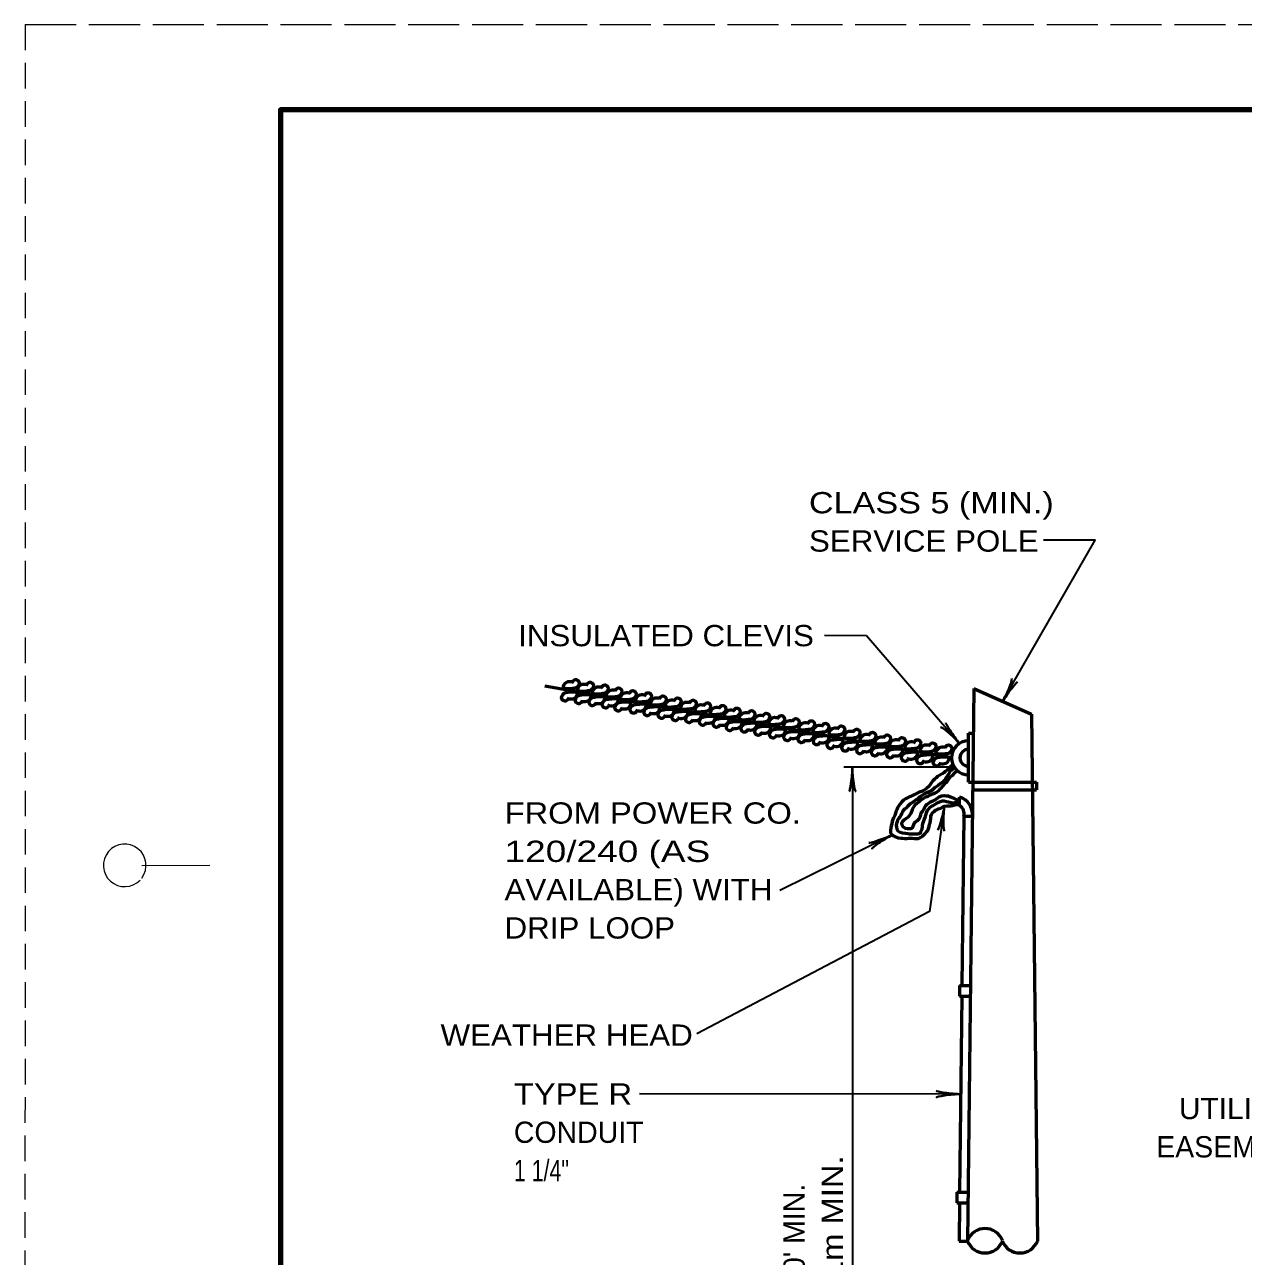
# Model space of a CAD drawing. Extents: x -68 to 612, y -58 to 382.
# Drawn here: x -67.7 to 75.5, y 237.5 to 382.2 of the extents above; entities that cross this region are included whole.
import ezdxf
from ezdxf.enums import TextEntityAlignment as Align

# ---------------------------------------------------------------- set-up
doc = ezdxf.new("R2010")
doc.units = 0
doc.linetypes.add('LONG_DASHED', pattern=[7.5, 6, -1.5])
doc.linetypes.add('MEDIUM_DASHED', pattern=[4.5, 3, -1.5])
doc.layers.add('1', color=7, linetype='Continuous', lineweight=53)
doc.layers.add('61', color=7, linetype='Continuous', lineweight=35)

msp = doc.modelspace()

# ---------------------------------------------------------------- linework, layer by layer
at = {"layer": '1', "linetype": 'MEDIUM_DASHED', "lineweight": 13}
msp.add_line((-67.611, 382.166), (-67.671, -57.874), dxfattribs=at)
at = {"layer": '1', "lineweight": 35}
for p, q in [((31.222, 310.386), (26.284, 310.397)), ((42.124, 297.726), (31.222, 310.386)), ((41.57, 294.939), (28.57, 294.939)), ((34.265, 286.976), (21.04, 280.461)), ((42.283, 256.525), (4.547, 256.554))]:
    msp.add_line(p, q, dxfattribs=at)
at = {"layer": '1'}
for p, q in [((41.199, 296.039), (-6.564, 304.461)), ((43.824, 304.163), (43.087, 239.264)), ((43.824, 304.163), (50.588, 301.163)), ((50.588, 301.163), (51.291, 239.264)), ((43.199, 298.914), (43.764, 298.914)), ((43.199, 293.164), (43.199, 298.914)), ((43.199, 293.164), (51.189, 293.164)), ((51.189, 293.164), (51.189, 292.264)), ((42.154, 290.426), (42.154, 291.426)), ((43.689, 292.264), (51.189, 292.264)), ((42.654, 289.176), (42.428, 269.275)), ((42.654, 289.176), (43.654, 289.176)), ((42.163, 269.275), (43.413, 269.275)), ((42.163, 269.275), (42.163, 268.025)), ((42.413, 268.025), (42.152, 245.025)), ((42.163, 268.025), (43.413, 268.025)), ((41.837, 245.025), (43.087, 245.025)), ((41.837, 245.025), (41.837, 243.775)), ((41.837, 243.775), (43.087, 243.775)), ((42.138, 243.775), (42.087, 239.275)), ((42.087, 239.275), (43.087, 239.275))]:
    msp.add_line(p, q, dxfattribs=at)
at = {"layer": '1', "lineweight": 35}
for points in [[(47.206, 302.663), (58.076, 321.589), (52.012, 321.589)], [(29.57, 294.939), (29.57, 176.275), (29.57, 116.264)], [(40.381, 290.343), (38.621, 277.993), (11.274, 263.595)]]:
    msp.add_lwpolyline(points, dxfattribs=at)
at = {"layer": '1'}
for points in [[(41.388, 295.302), (41.227, 295.14), (41.106, 295.02), (40.965, 294.858), (40.804, 294.697), (40.683, 294.576), (40.481, 294.435), (40.32, 294.274), (40.099, 294.173), (39.837, 293.991), (39.554, 293.83), (39.393, 293.669), (39.212, 293.528), (39.01, 293.326), (38.91, 293.185), (38.728, 292.943), (38.527, 292.681), (38.305, 292.48), (38.103, 292.318), (37.862, 292.177), (37.7, 292.097), (37.519, 292.036), (37.338, 291.955), (37.176, 291.875), (36.995, 291.774), (36.814, 291.693), (36.612, 291.593), (36.391, 291.512), (36.189, 291.411), (35.988, 291.31), (35.806, 291.21), (35.564, 291.048), (35.363, 290.847), (35.161, 290.625), (35.02, 290.403), (34.879, 290.161), (34.779, 289.92), (34.678, 289.698), (34.617, 289.496), (34.537, 289.254), (34.396, 288.992), (34.315, 288.791), (34.255, 288.549), (34.194, 288.287), (34.134, 288.045), (34.073, 287.783), (34.033, 287.541), (34.053, 287.218), (34.154, 287.077), (34.376, 286.876), (34.537, 286.775), (34.758, 286.714), (34.96, 286.654), (35.262, 286.614), (35.464, 286.594), (35.726, 286.573), (35.947, 286.573), (36.169, 286.594), (36.37, 286.594), (36.592, 286.614), (36.854, 286.573), (37.156, 286.553), (37.338, 286.573), (37.559, 286.674), (37.781, 286.835), (37.962, 286.976), (38.103, 287.158), (38.285, 287.339), (38.426, 287.501), (38.506, 287.743), (38.567, 287.984), (38.627, 288.226), (38.708, 288.408), (38.748, 288.67), (38.768, 288.932), (38.789, 289.194), (38.869, 289.395), (38.99, 289.577), (39.172, 289.738), (39.333, 289.899), (39.514, 289.98), (39.695, 290.061), (39.937, 290.141), (40.179, 290.262), (40.381, 290.343), (40.703, 290.403), (40.905, 290.383), (41.126, 290.403), (41.368, 290.444), (41.61, 290.504), (41.811, 290.544), (42.033, 290.565), (42.114, 290.585)], [(41.57, 294.939), (41.207, 294.596), (41.066, 294.455), (40.844, 294.133), (40.683, 293.891), (40.562, 293.729), (40.441, 293.427), (40.26, 293.266), (40.058, 293.125), (39.857, 292.963), (39.635, 292.782), (39.413, 292.641), (39.192, 292.52), (39.01, 292.298), (38.849, 292.177), (38.506, 291.996), (38.224, 291.895), (38.023, 291.794), (37.862, 291.673), (37.68, 291.572), (37.499, 291.452), (37.297, 291.27), (37.156, 291.169), (36.975, 291.048), (36.794, 290.907), (36.491, 290.726), (36.35, 290.625), (36.229, 290.504), (36.048, 290.303), (35.867, 290.121), (35.685, 290), (35.544, 289.839), (35.444, 289.657), (35.343, 289.456), (35.262, 289.274), (35.141, 289.073), (35, 288.932), (34.879, 288.73), (34.819, 288.529), (34.758, 288.327), (34.718, 288.105), (34.738, 287.884), (34.799, 287.642), (34.899, 287.44), (35.161, 287.299), (35.444, 287.238), (35.806, 287.178), (36.068, 287.138), (36.27, 287.118), (36.572, 287.097), (36.773, 287.097), (37.015, 287.097), (37.257, 287.118), (37.459, 287.158), (37.6, 287.299), (37.66, 287.46), (37.761, 287.682), (37.781, 287.924), (37.801, 288.105), (37.841, 288.307), (37.902, 288.529), (38.003, 288.77), (38.124, 289.033), (38.204, 289.315), (38.285, 289.577), (38.365, 289.819), (38.486, 290.02), (38.648, 290.182), (38.829, 290.303), (39.051, 290.444), (39.292, 290.585), (39.494, 290.706), (39.716, 290.827), (39.897, 290.887), (40.139, 290.968), (40.34, 290.968), (40.602, 290.907), (40.864, 290.847), (41.166, 290.806), (41.388, 290.766), (41.61, 290.786), (41.831, 290.827), (42.013, 290.887), (42.174, 290.927)], [(41.831, 294.576), (41.61, 294.314), (41.227, 293.931), (41.046, 293.75), (40.905, 293.568), (40.643, 293.226), (40.522, 293.104), (40.401, 292.984), (40.199, 292.762), (39.978, 292.48), (39.837, 292.339), (39.675, 292.157), (39.494, 292.016), (39.292, 291.895), (38.97, 291.754), (38.768, 291.673), (38.587, 291.593), (38.426, 291.512), (38.204, 291.411), (37.902, 291.25), (37.62, 291.089), (37.479, 290.968), (37.318, 290.827), (37.116, 290.665), (36.894, 290.484), (36.753, 290.222), (36.592, 289.94), (36.411, 289.496), (36.31, 289.355), (36.129, 289.073), (35.867, 288.892), (35.605, 288.71), (35.464, 288.569), (35.343, 288.347), (35.363, 288.146), (35.504, 287.964), (35.746, 287.783), (36.028, 287.743), (36.209, 287.743), (36.431, 287.743), (36.612, 287.823), (36.713, 288.025), (36.794, 288.206), (36.874, 288.387), (36.975, 288.529), (37.156, 288.65), (37.398, 288.851), (37.519, 289.113), (37.6, 289.355), (37.66, 289.557), (37.781, 289.738), (37.882, 289.899), (37.983, 290.061), (38.083, 290.242), (38.204, 290.444), (38.345, 290.585), (38.547, 290.726), (38.748, 290.847), (39.051, 290.968), (39.272, 291.109), (39.434, 291.23), (39.615, 291.351), (39.776, 291.452), (40.078, 291.552), (40.34, 291.593), (40.582, 291.572), (40.804, 291.552), (41.106, 291.472), (41.287, 291.391), (41.469, 291.29), (41.67, 291.169), (41.831, 291.089), (42.073, 290.988), (42.154, 290.968)]]:
    msp.add_lwpolyline(points, dxfattribs=at)
for centre, radius, start, end in [((43.199, 296.039), 2, 90, 270), ((43.199, 296.039), 1, 90, 270), ((41.555, 289.401), 2.111, 353.86968, 73.51046), ((41.614, 289.485), 1.085, 343.45685, 60.14597), ((45.138, 238.542), 2.204, 21.451, 158.54901), ((45.138, 240.07), 2.204, 201.45099, 338.549), ((49.24, 240.07), 2.204, 201.45099, 338.549)]:
    msp.add_arc(centre, radius, start, end, dxfattribs=at)
at = {"layer": '1', "lineweight": 40}
for centre, major_axis, ratio, start_param, end_param in [((47.51, 303.747), (-0.754, -1.626), 0.122415, 0.8963533, 3.1415927), ((47.51, 303.747), (-0.754, -1.626), 0.122415, 0.8963533, 3.1415927), ((47.948, 303.53), (1.027, 1.436), 0.07063, 6.2823074, 8.5597026), ((47.948, 303.53), (1.027, 1.436), 0.07063, 6.2823074, 8.5597026), ((41.203, 298.372), (1.284, -1.251), 0.122415, 0.8963533, 3.1415927), ((41.203, 298.372), (1.284, -1.251), 0.122415, 0.8963533, 3.1415927), ((41.554, 298.713), (1.013, -1.446), 0.07063, 3.1407148, 5.41811), ((41.554, 298.713), (1.013, -1.446), 0.07063, 3.1407148, 5.41811), ((29.358, 293.818), (0.176, 1.756), 0.07063, 3.1407148, 5.41811), ((29.358, 293.818), (0.176, 1.756), 0.07063, 3.1407148, 5.41811), ((29.358, 293.818), (0.176, 1.756), 0.07063, 3.1407148, 5.41811), ((29.846, 293.848), (-0.156, 1.786), 0.122415, 0.8963533, 3.1415927), ((29.846, 293.848), (-0.156, 1.786), 0.122415, 0.8963533, 3.1415927), ((29.846, 293.848), (-0.156, 1.786), 0.122415, 0.8963533, 3.1415927), ((40.013, 289.263), (-0.422, -1.714), 0.07063, 6.2823074, 8.5597026), ((40.013, 289.263), (-0.422, -1.714), 0.07063, 6.2823074, 8.5597026), ((40.5, 289.224), (0.097, 1.79), 0.122415, 0.8963533, 3.1415927), ((40.5, 289.224), (0.097, 1.79), 0.122415, 0.8963533, 3.1415927), ((33.166, 286.671), (-1.653, -0.619), 0.07063, 6.2823074, 8.5597026), ((33.166, 286.671), (-1.653, -0.619), 0.07063, 6.2823074, 8.5597026), ((33.408, 286.246), (1.533, 0.929), 0.122415, 0.8963533, 3.1415927), ((33.408, 286.246), (1.533, 0.929), 0.122415, 0.8963533, 3.1415927), ((41.191, 256.25), (1.786, 0.155), 0.122415, 0.8963533, 3.1415927), ((41.162, 256.738), (-1.756, 0.177), 0.07063, 6.2823074, 8.5597026)]:
    msp.add_ellipse(centre, major_axis=major_axis, ratio=ratio, start_param=start_param, end_param=end_param, dxfattribs=at)
at = {"layer": '1'}
for points in [[(-3.749, 303.067), (-4.183, 302.695), (-4.555, 302.943), (-4.308, 303.625), (-3.811, 303.749), (-2.757, 303.625), (-3.129, 303.005), (-3.749, 302.943)], [(-3.377, 304.866), (-2.943, 305.238), (-2.571, 304.99), (-2.819, 304.307), (-3.315, 304.183), (-4.37, 304.307), (-3.998, 304.928), (-3.377, 304.99)], [(-1.703, 304.556), (-1.269, 304.928), (-0.897, 304.68), (-1.145, 303.997), (-1.641, 303.873), (-2.695, 303.997), (-2.323, 304.618), (-1.703, 304.68)], [(0.033, 304.245), (0.467, 304.618), (0.84, 304.37), (0.592, 303.687), (0.095, 303.563), (-0.959, 303.687), (-0.587, 304.307), (0.033, 304.37)], [(1.646, 303.873), (2.08, 304.245), (2.452, 303.997), (2.204, 303.315), (1.708, 303.191), (0.653, 303.315), (1.026, 303.935), (1.646, 303.997)], [(3.32, 303.563), (3.754, 303.935), (4.126, 303.687), (3.878, 303.005), (3.382, 302.881), (2.328, 303.005), (2.7, 303.625), (3.32, 303.687)], [(-2.137, 302.757), (-2.571, 302.384), (-2.943, 302.632), (-2.695, 303.315), (-2.199, 303.439), (-1.145, 303.315), (-1.517, 302.695), (-2.137, 302.632)], [(-0.525, 302.508), (-0.959, 302.136), (-1.331, 302.384), (-1.083, 303.067), (-0.587, 303.191), (0.467, 303.067), (0.095, 302.446), (-0.525, 302.384)], [(1.026, 302.26), (0.592, 301.888), (0.22, 302.136), (0.468, 302.819), (0.964, 302.943), (2.018, 302.819), (1.646, 302.198), (1.026, 302.136)], [(2.514, 301.888), (2.08, 301.516), (1.708, 301.764), (1.956, 302.446), (2.452, 302.57), (3.506, 302.446), (3.134, 301.826), (2.514, 301.764)], [(4.312, 301.64), (3.878, 301.268), (3.506, 301.516), (3.754, 302.198), (4.25, 302.322), (5.305, 302.198), (4.933, 301.578), (4.312, 301.516)], [(5.119, 303.315), (5.553, 303.687), (5.925, 303.439), (5.677, 302.757), (5.18, 302.632), (4.126, 302.757), (4.498, 303.377), (5.119, 303.439)], [(6.855, 302.943), (7.289, 303.315), (7.661, 303.067), (7.413, 302.384), (6.917, 302.26), (5.863, 302.384), (6.235, 303.005), (6.855, 303.067)], [(8.591, 302.695), (9.025, 303.067), (9.397, 302.819), (9.149, 302.136), (8.653, 302.012), (7.599, 302.136), (7.971, 302.757), (8.591, 302.819)], [(10.39, 302.446), (10.824, 302.819), (11.196, 302.57), (10.948, 301.888), (10.452, 301.764), (9.397, 301.888), (9.77, 302.508), (10.39, 302.57)], [(12.064, 302.136), (12.498, 302.508), (12.87, 302.26), (12.622, 301.578), (12.126, 301.454), (11.072, 301.578), (11.444, 302.198), (12.064, 302.26)], [(5.925, 301.33), (5.491, 300.958), (5.119, 301.206), (5.367, 301.888), (5.863, 302.012), (6.917, 301.888), (6.545, 301.268), (5.925, 301.206)], [(7.599, 301.02), (7.165, 300.647), (6.793, 300.895), (7.041, 301.578), (7.537, 301.702), (8.591, 301.578), (8.219, 300.958), (7.599, 300.895)], [(9.211, 300.772), (8.777, 300.399), (8.405, 300.647), (8.653, 301.33), (9.149, 301.454), (10.204, 301.33), (9.832, 300.709), (9.211, 300.647)], [(10.824, 300.523), (10.39, 300.151), (10.018, 300.399), (10.266, 301.082), (10.762, 301.206), (11.816, 301.082), (11.444, 300.461), (10.824, 300.399)], [(12.436, 300.213), (12.002, 299.841), (11.63, 300.089), (11.878, 300.772), (12.374, 300.896), (13.428, 300.772), (13.056, 300.151), (12.436, 300.089)], [(13.862, 301.826), (14.296, 302.198), (14.669, 301.95), (14.421, 301.268), (13.924, 301.144), (12.87, 301.268), (13.242, 301.888), (13.862, 301.95)], [(15.537, 301.516), (15.971, 301.888), (16.343, 301.64), (16.095, 300.958), (15.599, 300.834), (14.545, 300.958), (14.917, 301.578), (15.537, 301.64)], [(17.273, 301.206), (17.707, 301.578), (18.079, 301.33), (17.831, 300.647), (17.335, 300.523), (16.281, 300.647), (16.653, 301.268), (17.273, 301.33)], [(19.01, 300.896), (19.444, 301.268), (19.816, 301.02), (19.568, 300.337), (19.072, 300.213), (18.017, 300.337), (18.389, 300.958), (19.01, 301.02)], [(20.746, 300.647), (21.18, 301.02), (21.552, 300.772), (21.304, 300.089), (20.808, 299.965), (19.754, 300.089), (20.126, 300.709), (20.746, 300.772)], [(14.049, 299.965), (13.614, 299.593), (13.242, 299.841), (13.49, 300.523), (13.987, 300.647), (15.041, 300.523), (14.669, 299.903), (14.049, 299.841)], [(15.599, 299.593), (15.165, 299.221), (14.793, 299.469), (15.041, 300.151), (15.537, 300.275), (16.591, 300.151), (16.219, 299.531), (15.599, 299.469)], [(17.335, 299.407), (16.901, 299.035), (16.529, 299.283), (16.777, 299.965), (17.273, 300.089), (18.328, 299.965), (17.955, 299.345), (17.335, 299.283)], [(18.948, 299.034), (18.514, 298.662), (18.142, 298.91), (18.389, 299.593), (18.886, 299.717), (19.94, 299.593), (19.568, 298.972), (18.948, 298.91)], [(20.684, 298.724), (20.25, 298.352), (19.878, 298.6), (20.126, 299.283), (20.622, 299.407), (21.676, 299.283), (21.304, 298.662), (20.684, 298.6)], [(22.482, 300.275), (22.916, 300.647), (23.288, 300.399), (23.04, 299.717), (22.544, 299.593), (21.49, 299.717), (21.862, 300.337), (22.482, 300.399)], [(24.281, 300.027), (24.715, 300.399), (25.087, 300.151), (24.839, 299.469), (24.343, 299.345), (23.289, 299.469), (23.661, 300.089), (24.281, 300.151)], [(25.955, 299.717), (26.389, 300.089), (26.761, 299.841), (26.513, 299.159), (26.017, 299.034), (24.963, 299.159), (25.335, 299.779), (25.955, 299.841)], [(27.816, 299.407), (28.25, 299.779), (28.622, 299.531), (28.374, 298.848), (27.877, 298.724), (26.823, 298.848), (27.195, 299.469), (27.816, 299.531)], [(22.358, 298.414), (21.924, 298.042), (21.552, 298.29), (21.8, 298.972), (22.296, 299.097), (23.351, 298.972), (22.979, 298.352), (22.358, 298.29)], [(24.033, 298.166), (23.599, 297.794), (23.227, 298.042), (23.475, 298.724), (23.971, 298.849), (25.025, 298.724), (24.653, 298.104), (24.033, 298.042)], [(25.831, 297.918), (25.397, 297.546), (25.025, 297.794), (25.273, 298.476), (25.769, 298.6), (26.823, 298.476), (26.451, 297.856), (25.831, 297.794)], [(27.444, 297.484), (27.009, 297.111), (26.637, 297.36), (26.885, 298.042), (27.382, 298.166), (28.436, 298.042), (28.064, 297.422), (27.444, 297.36)], [(29.614, 299.035), (30.048, 299.407), (30.42, 299.159), (30.172, 298.476), (29.676, 298.352), (28.622, 298.476), (28.994, 299.097), (29.614, 299.159)], [(31.474, 298.662), (31.908, 299.034), (32.28, 298.786), (32.032, 298.104), (31.536, 297.98), (30.482, 298.104), (30.854, 298.724), (31.474, 298.786)], [(33.211, 298.352), (33.645, 298.724), (34.017, 298.476), (33.769, 297.794), (33.273, 297.67), (32.219, 297.794), (32.591, 298.414), (33.211, 298.476)], [(34.947, 298.042), (35.381, 298.414), (35.753, 298.166), (35.505, 297.484), (35.009, 297.36), (33.955, 297.484), (34.327, 298.104), (34.947, 298.166)], [(36.745, 297.794), (37.18, 298.166), (37.552, 297.918), (37.304, 297.236), (36.807, 297.111), (35.753, 297.236), (36.125, 297.856), (36.745, 297.918)], [(29.18, 297.173), (28.746, 296.801), (28.374, 297.049), (28.622, 297.732), (29.118, 297.856), (30.172, 297.732), (29.8, 297.111), (29.18, 297.049)], [(30.916, 296.863), (30.482, 296.491), (30.11, 296.739), (30.358, 297.422), (30.854, 297.546), (31.909, 297.422), (31.536, 296.801), (30.916, 296.739)], [(32.653, 296.615), (32.219, 296.243), (31.847, 296.491), (32.095, 297.174), (32.591, 297.298), (33.645, 297.174), (33.273, 296.553), (32.653, 296.491)], [(34.451, 296.367), (34.017, 295.995), (33.645, 296.243), (33.893, 296.925), (34.389, 297.049), (35.443, 296.925), (35.071, 296.305), (34.451, 296.243)], [(36.188, 295.995), (35.753, 295.623), (35.381, 295.871), (35.629, 296.553), (36.126, 296.677), (37.18, 296.553), (36.808, 295.933), (36.188, 295.871)], [(38.544, 297.422), (38.978, 297.794), (39.35, 297.546), (39.102, 296.863), (38.606, 296.739), (37.552, 296.863), (37.924, 297.484), (38.544, 297.546)], [(40.404, 297.174), (40.838, 297.546), (41.21, 297.298), (40.962, 296.615), (40.466, 296.491), (39.412, 296.615), (39.784, 297.236), (40.404, 297.298)], [(37.986, 295.685), (37.552, 295.312), (37.18, 295.561), (37.428, 296.243), (37.924, 296.367), (38.978, 296.243), (38.606, 295.623), (37.986, 295.561)], [(39.908, 295.437), (39.474, 295.064), (39.102, 295.312), (39.35, 295.995), (39.846, 296.119), (40.901, 295.995), (40.528, 295.375), (39.908, 295.312)]]:
    msp.add_spline(points, degree=3, dxfattribs=at)
at = {"layer": '61', "linetype": 'LONG_DASHED', "lineweight": 13}
msp.add_line((-67.611, 382.166), (612.409, 382.166), dxfattribs=at)
at = {"layer": '61', "lineweight": 13}
msp.add_line((-53.891, 283.406), (-45.911, 283.426), dxfattribs=at)
at = {"layer": '61', "lineweight": 158}
msp.add_lwpolyline([(601.429, 372.166), (-37.611, 372.166), (-37.611, -47.854)], dxfattribs=at)
at = {"layer": '61', "lineweight": 13}
msp.add_arc((-55.914, 283.407), 2.5, 323.13009, 316.23216, dxfattribs=at)

# ---------------------------------------------------------------- texts
at = {"layer": '1'}
for s, width, p in [('CLASS 5 (MIN.)', 1.2, (24.462, 324.756)), ('SERVICE POLE', 1.1, (24.462, 320.256)), ('INSULATED CLEVIS', 1.1, (-9.701, 309.144)), ('FROM POWER CO.', 1.15, (-11.296, 288.303)), ('120/240 (AS', 1.3, (-11.296, 283.803)), ('AVAILABLE) WITH', 1.1, (-11.296, 279.303)), ('DRIP LOOP', 1.1, (-11.296, 274.803)), ('WEATHER HEAD', 1.1, (-18.812, 262.211)), ('TYPE R', 1.15, (-10.2, 255.302)), ('1 1/4"', 0.75, (-10.2, 246.302))]:
    msp.add_text(s, height=2.5, dxfattribs=dict(at, width=width)).set_placement(p)
at = {"layer": '1', "width": 1.05}
msp.add_text('UTILITY', height=2.5, dxfattribs=at).set_placement((74.452, 253.593), align=Align.CENTER)
at = {"layer": '1'}
msp.add_text('CONDUIT', height=2.5, dxfattribs=at).set_placement((-10.2, 250.802))
msp.add_text('EASEMENT', height=2.5, dxfattribs=at).set_placement((74.452, 249.093), align=Align.CENTER)
at = {"layer": '1', "width": 1.15}
msp.add_text('(6.1m MIN.', height=2.5, rotation=90, dxfattribs=at).set_placement((28.469, 239.825), align=Align.CENTER)
at = {"layer": '1'}
msp.add_text("20' MIN.", height=2.5, rotation=90, dxfattribs=at).set_placement((23.969, 239.825), align=Align.CENTER)

doc.saveas('drawing.dxf')
